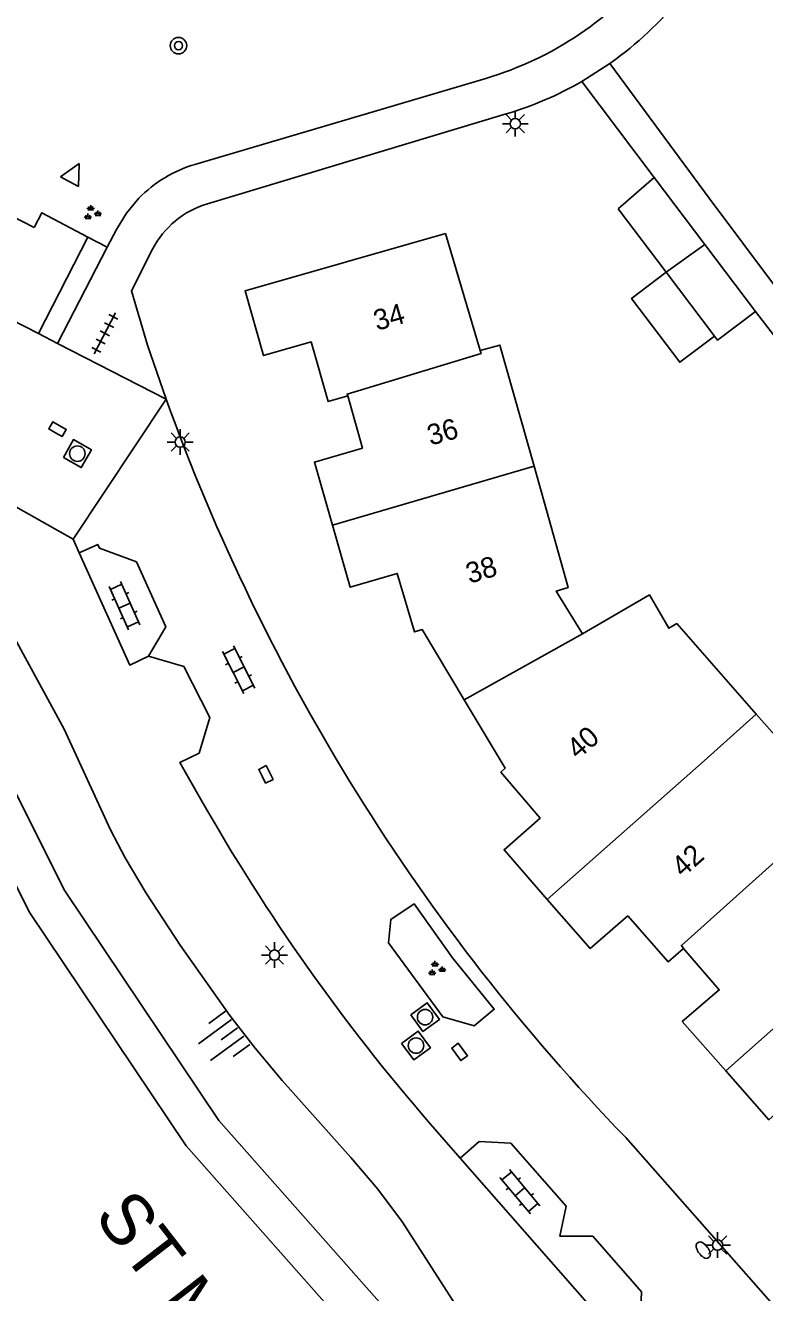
# Model space of a CAD drawing. Extents: x 126000 to 131009, y 393000 to 395500.
# Drawn here: x 130482.9 to 130518.8, y 394946.8 to 395008.4 of the extents above; entities that cross this region are included whole.
import ezdxf

# ---------------------------------------------------------------- set-up
doc = ezdxf.new("R2010")
doc.units = 0
for name, color, linetype in [('gg-afsc-erfafscheiding', 7, 'Continuous'), ('gg-anno-huisnummerreeks BGT', 7, 'Continuous'), ('gg-anno-naam water', 7, 'Continuous'), ('gg-bbg-bijgebouw', 7, 'Continuous'), ('gg-bbg-gedigitaliseerde bebouwing', 7, 'Continuous'), ('gg-bbg-gedigitaliseerde bijgebouw', 7, 'Continuous'), ('gg-bbg-hoofdgebouw', 7, 'Continuous'), ('gg-bbg-luifel en loopbrug', 7, 'Continuous'), ('gg-bbg-tussenscheiding', 7, 'Continuous'), ('gg-knt-BGT kruinlijn', 7, 'Continuous'), ('gg-knt-verharding', 7, 'Continuous'), ('gg-knt-verharding nz', 7, 'Continuous'), ('gg-kntw-beschoeiing', 7, 'Continuous'), ('gt-grn-groengrens', 7, 'Continuous'), ('gt-grn-weggrens', 7, 'Continuous'), ('gt-symb-boom', 7, 'Continuous'), ('gt-symb-brandkraan', 7, 'Continuous'), ('gt-symb-groenvak', 7, 'Continuous'), ('gt-symb-klinker verharding', 7, 'Continuous'), ('gt-symb-kolk', 7, 'Continuous'), ('gt-symb-lichtmast', 7, 'Continuous'), ('gt-symb-rioolschacht', 7, 'Continuous'), ('gt-symb-talud symbool', 7, 'Continuous'), ('gt-symb-tegel verharding', 7, 'Continuous'), ('gt-symb-waterafsluiter', 7, 'Continuous')]:
    doc.layers.add(name, color=color, linetype=linetype)

# ---------------------------------------------------------------- blocks, each defined once
blk = doc.blocks.new('gt0-BOOM')
at = {"layer": 'gt-symb-boom'}
for radius in [0.4, 0.2]:
    blk.add_circle((0, 0), radius, dxfattribs=at)
blk = doc.blocks.new('gt0-LMAST')
at = {"layer": 'gt-symb-lichtmast'}
for p, q in [((-0.005, 0.246), (-0.005, 0.621)), ((-0.182, 0.173), (-0.447, 0.438)), ((0.172, 0.173), (0.437, 0.438)), ((-0.255, -0.004), (-0.63, -0.004)), ((-0.182, -0.181), (-0.447, -0.446)), ((-0.005, -0.254), (-0.005, -0.629)), ((0.437, -0.446), (0.172, -0.181)), ((0.245, -0.004), (0.62, -0.004))]:
    blk.add_line(p, q, dxfattribs=at)
blk.add_circle((-0.005, -0.004), 0.25, dxfattribs=at)
blk = doc.blocks.new('gt0-GRVAK')
at = {"layer": 'gt-symb-groenvak'}
for p, q in [((-0.11, 0.189), (-0.228, 0.24)), ((-0.182, 0.153), (0.088, 0.153)), ((-0.091, 0.211), (-0.156, 0.322)), ((-0.047, 0.214), (-0.047, 0.393)), ((-0.004, 0.211), (0.061, 0.322)), ((0.015, 0.189), (0.133, 0.24)), ((0.262, -0.052), (0.197, 0.059)), ((0.305, -0.049), (0.305, 0.13)), ((0.349, -0.052), (0.414, 0.059)), ((-0.245, -0.228), (-0.363, -0.177)), ((-0.318, -0.264), (-0.047, -0.264)), ((-0.226, -0.206), (-0.291, -0.095)), ((-0.183, -0.203), (-0.183, -0.024)), ((-0.139, -0.206), (-0.074, -0.095)), ((-0.12, -0.228), (-0.002, -0.177)), ((0.243, -0.074), (0.125, -0.023)), ((0.17, -0.11), (0.441, -0.11)), ((0.368, -0.074), (0.486, -0.023))]:
    blk.add_line(p, q, dxfattribs=at)
blk = doc.blocks.new('gt0-RS')
at = {"layer": 'gt-symb-rioolschacht'}
blk.add_lwpolyline([(-0.5, -0.5), (0.5, -0.5), (0.5, 0.5), (-0.5, 0.5)], close=True, dxfattribs=at)
blk.add_circle((0, 0), 0.375, dxfattribs=at)
blk = doc.blocks.new('gt0-KL1')
at = {"layer": 'gt-symb-klinker verharding'}
for p, q in [((-1.15, 0.3), (1.15, 0.3)), ((-1, -0.3), (-1, 0.3)), ((-0.5, 0.3), (-0.5, 0.45)), ((0, -0.3), (0, 0.3)), ((0.5, 0.3), (0.5, 0.45)), ((1, -0.3), (1, 0.3)), ((-1.15, -0.3), (1.15, -0.3)), ((-0.5, -0.45), (-0.5, -0.3)), ((0.5, -0.45), (0.5, -0.3))]:
    blk.add_line(p, q, dxfattribs=at)
blk = doc.blocks.new('gt0-KOLK')
at = {"layer": 'gt-symb-kolk'}
blk.add_lwpolyline([(0, 0), (0.375, 0), (0.375, 0.4), (-0.375, 0.4), (-0.375, 0), (0, 0)], dxfattribs=at)
blk = doc.blocks.new('gt0-BR')
at = {"layer": 'gt-symb-brandkraan'}
for centre, radius, start, end in [((-0.244, 0), 0.206, 107.56694, 252.43307), ((0.599, -2.664), 3, 106.89205, 107.56694), ((0, -0.691), 0.938, 73.10799, 106.89205), ((-0.599, -2.664), 3, 72.43309, 73.10799), ((0.244, 0), 0.206, 287.56695, 72.43309), ((0.599, 2.664), 3, 252.43307, 253.10797), ((0, 0.691), 0.938, 253.10797, 286.89206), ((-0.599, 2.664), 3, 286.89206, 287.56695)]:
    blk.add_arc(centre, radius, start, end, dxfattribs=at)
blk = doc.blocks.new('gt0-TALUD_1')
at = {"layer": 'gt-symb-talud symbool'}
for p, q in [((-1, -1), (-1, 0)), ((-0.5, -2), (-0.5, 0)), ((0, -1), (0, 0)), ((0.5, -2), (0.5, 0)), ((1, -1), (1, 0))]:
    blk.add_line(p, q, dxfattribs=at)
blk = doc.blocks.new('gt0-WAFSL')
at = {"layer": 'gt-symb-waterafsluiter'}
for p, q in [((-0.5, -0.333), (0, 0.667)), ((0, 0.667), (0.5, -0.333)), ((0.5, -0.333), (-0.5, -0.333))]:
    blk.add_line(p, q, dxfattribs=at)
blk = doc.blocks.new('gt0-TEG1')
at = {"layer": 'gt-symb-tegel verharding'}
for p, q in [((-1.125, 0), (1.125, 0)), ((-0.9, -0.25), (-0.9, 0.25)), ((-0.45, -0.25), (-0.45, 0.25)), ((0, -0.25), (0, 0.25)), ((0.45, -0.25), (0.45, 0.25)), ((0.9, -0.25), (0.9, 0.25))]:
    blk.add_line(p, q, dxfattribs=at)

msp = doc.modelspace()

# ---------------------------------------------------------------- linework, layer by layer
at = {"layer": 'gg-afsc-erfafscheiding'}
for p, q in [((130511.569, 395006.757), (130511.273, 395006.541)), ((130511.273, 395006.541), (130516.105, 395000)), ((130513.432, 395001.011), (130509.914, 395005.666)), ((130518.346, 394994.504), (130528.53, 394981.27))]:
    msp.add_line(p, q, dxfattribs=at)
msp.add_lwpolyline([(130516.105, 395000), (130527.64, 394984.57), (130535.94, 394975.18), (130545.66, 394964.1), (130551.495, 394958.025)], dxfattribs=at)
msp.add_arc((130501.254, 395020.739), 17.375, 306.41656, 321.72801, dxfattribs=at)
at = {"layer": 'gg-bbg-bijgebouw'}
for p, q in [((130513.432, 395001.011), (130511.689, 394999.486)), ((130515.892, 394997.753), (130513.432, 395001.011)), ((130515.892, 394997.753), (130518.346, 394994.504))]:
    msp.add_line(p, q, dxfattribs=at)
at = {"layer": 'gg-bbg-gedigitaliseerde bebouwing'}
for p, q in [((130504.98, 394992.6), (130503.298, 394998.287)), ((130518.391, 394974.945), (130522.308, 394970.49))]:
    msp.add_line(p, q, dxfattribs=at)
for points in [[(130504.98, 394992.6), (130505.93, 394992.87), (130507.595, 394986.979)], [(130507.595, 394986.979), (130509.26, 394981.09), (130508.67, 394980.92), (130509.956, 394978.848)], [(130509.956, 394978.848), (130513.199, 394980.73), (130514.139, 394979.11), (130514.529, 394979.337), (130518.391, 394974.945)]]:
    msp.add_lwpolyline(points, dxfattribs=at)
at = {"layer": 'gg-bbg-gedigitaliseerde bijgebouw'}
for p, q in [((130511.689, 394999.486), (130514.016, 394996.404)), ((130514.016, 394996.404), (130516.358, 394993.304))]:
    msp.add_line(p, q, dxfattribs=at)
msp.add_lwpolyline([(130516.358, 394993.304), (130516.503, 394993.112), (130518.346, 394994.504)], dxfattribs=at)
at = {"layer": 'gg-bbg-hoofdgebouw'}
for points in [[(130503.298, 394998.287), (130493.554, 394995.5), (130494.458, 394992.359), (130496.765, 394993.017), (130497.588, 394990.133), (130498.542, 394990.399)], [(130498.542, 394990.399), (130499.253, 394987.852), (130496.927, 394987.187), (130497.806, 394984.113)], [(130497.806, 394984.113), (130498.667, 394981.103), (130500.944, 394981.779), (130501.789, 394978.932), (130502.167, 394979.045), (130504.205, 394975.631)], [(130504.205, 394975.631), (130506.188, 394972.31), (130505.984, 394972.117), (130507.891, 394969.896), (130506.142, 394968.355), (130508.238, 394965.947)], [(130508.238, 394965.947), (130510.315, 394963.56), (130512.144, 394965.141), (130514.114, 394962.907), (130514.858, 394963.557)], [(130514.858, 394963.557), (130516.593, 394961.547), (130514.79, 394960.007), (130516.905, 394957.61)], [(130516.905, 394957.61), (130518.994, 394955.243), (130520.776, 394956.819), (130522.536, 394954.83)]]:
    msp.add_lwpolyline(points, dxfattribs=at)
at = {"layer": 'gg-bbg-luifel en loopbrug'}
msp.add_lwpolyline([(130516.358, 394993.304), (130514.672, 394992.03), (130512.33, 394995.13), (130514.016, 394996.404)], dxfattribs=at)
at = {"layer": 'gg-bbg-tussenscheiding'}
for p, q in [((130515.892, 394997.753), (130514.016, 394996.404)), ((130497.806, 394984.113), (130507.595, 394986.979)), ((130504.205, 394975.631), (130509.956, 394978.848))]:
    msp.add_line(p, q, dxfattribs=at)
for points in [[(130504.98, 394992.6), (130505.02, 394992.45), (130498.51, 394990.49), (130498.542, 394990.399)], [(130508.238, 394965.947), (130515.853, 394972.682), (130518.391, 394974.945)], [(130522.308, 394970.49), (130520.5, 394968.9), (130520.43, 394968.99), (130519.68, 394968.33), (130519.78, 394968.21), (130514.75, 394963.71), (130514.858, 394963.557)], [(130516.905, 394957.61), (130524.5, 394964.36), (130527.375, 394966.888)]]:
    msp.add_lwpolyline(points, dxfattribs=at)
at = {"layer": 'gg-knt-BGT kruinlijn'}
msp.add_lwpolyline([(130482.373, 394978.622), (130484.767, 394974.219), (130487.015, 394969.322), (130487.737, 394967.959), (130488.759, 394966.24), (130490.407, 394963.726), (130492.824, 394960.298), (130494.044, 394958.714), (130495.356, 394957.145), (130498.7, 394953.416), (130500, 394951.874), (130501.209, 394950.266), (130503.916, 394946.052)], dxfattribs=at)
at = {"layer": 'gg-knt-verharding'}
for p, q in [((130505.245, 395005.817), (130491.124, 395001.643)), ((130506.243, 395004.092), (130491.727, 394999.732)), ((130485.926, 394998.11), (130486.863, 394997.616)), ((130484.445, 394992.947), (130486.863, 394997.616)), ((130489.726, 394990.235), (130484.445, 394992.947)), ((130485.198, 394983.441), (130485.496, 394982.782)), ((130504.007, 394953.384), (130502.569, 394955.026)), ((130512.046, 394954.375), (130535.485, 394927.832))]:
    msp.add_line(p, q, dxfattribs=at)
for points in [[(130485.926, 394998.11), (130483.69, 394999.29), (130483.303, 394998.582), (130479.293, 395000.633)], [(130486.863, 394997.616), (130487.307, 394998.478), (130487.797, 394999.28), (130488.401, 395000)], [(130489.726, 394990.235), (130488.823, 394992.856), (130488.038, 394995.504), (130489.064, 394997.522)], [(130461.574, 394963.462), (130459.38, 394968.208), (130457.804, 394967.551), (130457.087, 394967.861), (130455.351, 394972.368), (130455.653, 394973.117), (130457.21, 394973.737), (130455.629, 394977.766), (130458.694, 394982.531), (130479.355, 394986.73), (130485.198, 394983.441)], [(130485.496, 394982.782), (130487.962, 394977.321), (130488.868, 394977.765)], [(130488.868, 394977.765), (130490.587, 394977.256), (130491.845, 394974.776), (130491.324, 394973.047), (130490.391, 394972.594), (130491.397, 394970.824)], [(130500.519, 394963.838), (130500.635, 394964.97), (130501.766, 394965.736), (130503.637, 394963.114), (130505.659, 394960.606), (130504.685, 394959.802), (130503.158, 394960.241), (130500.519, 394963.838)], [(130512.734, 394944.928), (130512.03, 394944.228), (130504.007, 394953.384)]]:
    msp.add_lwpolyline(points, dxfattribs=at)
for centre, radius, start, end in [((130500.571, 395021.629), 16.488, 286.46885, 321.62612), ((130501.47, 395020.291), 16.887, 286.41635, 299.99967), ((130492.913, 394995.6), 6.302, 106.4909, 135.72086), ((130493.006, 394995.482), 4.439, 106.74565, 152.63231), ((130584.549, 395024.379), 100.783, 199.80283, 223.99513), ((130576.392, 395019.081), 97.739, 209.58645, 220.94778)]:
    msp.add_arc(centre, radius, start, end, dxfattribs=at)
at = {"layer": 'gg-knt-verharding nz'}
for p, q in [((130483.519, 394993.422), (130477.199, 394996.668)), ((130484.445, 394992.947), (130483.519, 394993.422))]:
    msp.add_line(p, q, dxfattribs=at)
for points in [[(130488.868, 394977.765), (130489.707, 394979.187), (130488.276, 394982.338), (130486.482, 394983.001), (130486.398, 394983.182), (130485.496, 394982.782)], [(130512.734, 394944.928), (130512.819, 394946.881), (130510.445, 394949.595), (130508.848, 394949.592), (130509.147, 394951.049), (130506.463, 394954.105), (130504.935, 394954.189), (130504.007, 394953.384)]]:
    msp.add_lwpolyline(points, dxfattribs=at)
at = {"layer": 'gg-kntw-beschoeiing'}
msp.add_lwpolyline([(130472.391, 394977.803), (130474.386, 394978.186), (130476.629, 394977.352), (130477.943, 394975.564), (130483.065, 394965.347), (130490.699, 394953.982), (130509.459, 394932.769)], dxfattribs=at)
at = {"layer": 'gt-grn-groengrens'}
msp.add_lwpolyline([(130464.128, 394970.483), (130463.997, 394970.751), (130464.264, 394974.756), (130466.523, 394979.247), (130473.608, 394980.609), (130477.887, 394979.018), (130479.655, 394976.612), (130484.796, 394966.357), (130492.285, 394955.207), (130511.216, 394933.8)], dxfattribs=at)
at = {"layer": 'gt-grn-weggrens'}
for p, q in [((130511.273, 395006.541), (130509.914, 395005.666)), ((130485.926, 394998.11), (130483.519, 394993.422)), ((130489.726, 394990.235), (130485.198, 394983.441))]:
    msp.add_line(p, q, dxfattribs=at)

# ---------------------------------------------------------------- block references
at = {"layer": 'gt-symb-boom'}
msp.add_blockref('gt0-BOOM', (130490.322, 395007.411), dxfattribs=at)
at = {"layer": 'gt-symb-brandkraan', "rotation": -53.70304105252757}
msp.add_blockref('gt0-BR', (130515.813, 394948.908), dxfattribs=at)
at = {"layer": 'gt-symb-groenvak'}
for p in [(130486.103, 394999.275), (130502.829, 394962.562)]:
    msp.add_blockref('gt0-GRVAK', p, dxfattribs=at)
at = {"layer": 'gt-symb-klinker verharding'}
for p, rotation in [((130487.704, 394980.212), -65.86887479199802), ((130493.241, 394977.1), -63.12746101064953), ((130506.908, 394951.746), 130.21618137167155)]:
    msp.add_blockref('gt0-KL1', p, dxfattribs=dict(at, rotation=rotation))
at = {"layer": 'gt-symb-kolk'}
for p, rotation in [((130484.345, 394988.61), -29.95108263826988), ((130494.387, 394971.926), -63.07637464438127), ((130503.815, 394958.42), -53.7030410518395)]:
    msp.add_blockref('gt0-KOLK', p, dxfattribs=dict(at, rotation=rotation))
at = {"layer": 'gt-symb-lichtmast'}
for p in [(130506.688, 395003.624), (130490.409, 394988.16), (130494.991, 394963.243), (130516.517, 394949.16)]:
    msp.add_blockref('gt0-LMAST', p, dxfattribs=at)
at = {"layer": 'gt-symb-rioolschacht'}
for p, rotation in [((130485.409, 394987.595), -29.410819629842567), ((130502.302, 394960.223), -53.7030410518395), ((130501.862, 394958.845), -53.70304105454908)]:
    msp.add_blockref('gt0-RS', p, dxfattribs=dict(at, rotation=rotation))
at = {"layer": 'gt-symb-talud symbool', "xscale": 0.9998369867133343, "yscale": 0.999836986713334, "rotation": -53.622932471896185}
msp.add_blockref('gt0-TALUD_1', (130493.194, 394959.71), dxfattribs=at)
at = {"layer": 'gt-symb-tegel verharding', "rotation": 62.48693881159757}
msp.add_blockref('gt0-TEG1', (130486.745, 394993.437), dxfattribs=at)
at = {"layer": 'gt-symb-waterafsluiter', "rotation": -27.846622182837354}
msp.add_blockref('gt0-WAFSL', (130485.186, 395001.101), dxfattribs=at)

# ---------------------------------------------------------------- texts
at = {"layer": 'gg-anno-huisnummerreeks BGT'}
for s, rotation, p in [('34', 15.9, (130499.964, 394993.551)), ('36', 15.6, (130502.564, 394987.978)), ('38', 16.6, (130504.456, 394981.27)), ('40', 40.6, (130509.72, 394972.712)), ('42', 41.4, (130514.822, 394966.977))]:
    msp.add_text(s, height=1, rotation=rotation, dxfattribs=at).set_placement(p)
at = {"layer": 'gg-anno-naam water'}
msp.add_text('ST MAARTENSLOOPVIJVER', height=2.5, rotation=307.72927, dxfattribs=at).set_placement((130486.172, 394950.538))

doc.saveas('drawing.dxf')
